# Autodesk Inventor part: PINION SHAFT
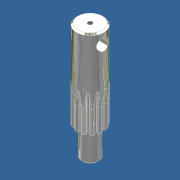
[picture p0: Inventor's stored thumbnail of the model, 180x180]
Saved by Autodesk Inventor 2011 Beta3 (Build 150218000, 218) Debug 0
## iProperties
Shininess: 64.0
Length Units: 11269
Angle Units: 11279
Time Units: 11290
Mass Units: 11283
Length Display Precision: 3
Angle Display Precision: 2
Compacted: True
Part Number: PINION SHAFT
Document SubType Name: Modeling
Created: 2003-10
Designer: Autodesk, Inc.
Manufacturer: Standard
Standards Organization: Custom
Mass: 506.446 g
Surface Area: 152.229 cm^2
Volume: 64.5977 cm^3
Density: 7.84 g/cm^3
Material: Steel, High Strength Low Alloy
Density: 0.0
Volumn: 0.0
Area: 0.0
PropertySet Name: Model Information
Control State: 0
Master: False
Checked Out: False
Author: Autodesk, Inc.
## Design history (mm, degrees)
sketch "Sketch1" dims "d4" = 6.7945 (= Big_R), "d5" = 5.54567 (= 2 x little_r)
  geometry: L1 (0, 12.7)-(5.815, 12.7); L2 (5.815, 12.7)-(5.815, 14.817); L3 (5.815, 14.817)-(0, 14.817); L4 (0, 14.817)-(0, 12.7); L5 (-8.163, 9.729)-(5.815, 14.817); L6 (0, 0)-(0, 10.251); L7 (0, 11.934)-(0, 12.7); L8 (0, 11.934)-(0, 10.251); L9 (-0.191, 11.933)-(-0.184, 10.731); L10 (0, 0)-(1.934, 14.69); L11 (0, 0)-(-1.338, 10.163); L12 (0, 0)-(3.923, 9.471); L13 (3.273, 11.477)-(2.955, 10.318); L14 (-0.181, 10.249)-(-0.184, 10.731); A1 r 12.7 centre (0, 0) between (0, 12.7) and (-8.163, 9.729); A2 r 14.817 centre (0, 0) between (0, 14.817) and (1.934, 14.69); A3 r 11.934 centre (0, 0) between (0, 11.934) and (6.294, 10.14); A4 r 10.251 centre (0, 0) between (0, 10.251) and (-0.181, 10.249); A5 r 6.795 centre (6.294, 10.14) between (1.365, 14.817) and (0, 12.7); A6 r 2.773 centre (2.568, 11.654) between (0, 12.7) and (-0.191, 11.933); A7 r 10.251 centre (0, 0) between (-0.651, 10.23) and (-1.338, 10.163); A8 r 0.498 centre (-0.682, 10.728) between (-0.651, 10.23) and (-0.184, 10.731); A9 r 10.251 centre (0, 0) between (3.923, 9.471) and (3.276, 9.713); A10 r 0.498 centre (3.435, 10.186) between (2.955, 10.318) and (3.276, 9.713); A11 r 2.773 centre (0.536, 11.922) between (3.273, 11.477) and (3.287, 12.267); A12 r 6.795 centre (-3.455, 11.423) between (3.287, 12.267) and (2.516, 14.665); A13 r 14.879 centre (0, 0) between (2.516, 14.665) and (1.365, 14.817); 2 further points; 1 other entity
  constraints: 30 point on circle, 28 end point, 13 centre point, 9 coincident, 9 symmetric about line, 4 tangent, 3 point on line, 2 parallel, 2 vertical, 1 collinear, 1 horizontal, 1 perpendicular, 16 other
  dimensions: "d0" = 25.4 diameter of A1 (= Pitch_Diameter); "d1" = 2.11667 distance of L1.end L2.end (= Addendum); "d2" = 20 deg angle of L1 L5 (= Tooth_Form); "d3" = 4.56565 distance of L6.end L3.end (= Whole_Depth); "d6" = 7.5 deg angle of L10 L6 (= mirror_angle); "d7" = 7.5 deg angle of L11 L6 (= mirror_angle); "d8" = 0.49848 radius of A8 (= Root_Fillet)
extrude "Extrusion1" new body sketch "Sketch1" distance "d9" = 25.4; taper "d10" = 0 deg
pattern_circular "Circular Pattern1" dims angle "d13" = 360 deg
sketch "Sketch2"
  geometry: C1 r 14.879 at (0, 0); 1 further point
  constraints: 1 centre point, 1 coincident
  dimensions: "d14" = 29.758 diameter of C1
extrude "Extrusion2" join sketch "Sketch2" distance "d15" = 71.4502; taper "d16" = 0 deg
sketch "Sketch3"
  geometry: C1 r 9.5 at (0, 0); 1 further point
  constraints: 1 centre point, 1 coincident
  dimensions: "d17" = 18.9992 diameter of C1
extrude "Extrusion3" join sketch "Sketch3" distance "d18" = 30.1498; taper "d19" = 0 deg
chamfer "Chamfer1" distance "d20" = 1.5875; stored, may be unused: second distance "d21" = 2, angle "d67" = 45 deg
chamfer "Chamfer2" distance "d22" = 1.5875; stored, may be unused: second distance "d23" = 2, angle "d68" = 45 deg
workplane "Work Plane2"
sketch "Sketch4"
  geometry: L1 (-13.292, 96.85)-(13.292, 96.85) reference; L2 (0, 96.85)-(0, 65.832); C1 r 6.54 at (0, 84.15)
  constraints: 2 end point, 1 centre point, 1 midpoint, 1 perpendicular, 1 point on line
  dimensions: "d26" = 13.081 diameter of C1; "d27" = 12.7 distance from line of L1 C1.centre
extrude "Extrusion4" cut sketch "Sketch4" distance "d28" = 50.8; taper "d29" = 0 deg
workplane "Work Plane3"
sketch "Sketch10"
  geometry: L1 (-5.206, 9.385)-(-5.801, 10.429) reference; L2 (-3.273, 11.477)-(-2.955, 10.318) reference; L3 (-5.801, 10.429)-(-5.206, 9.385); L4 (-2.955, 10.318)-(-3.273, 11.477); L5 (-30.301, 30.745)-(3.482, 44.738); L6 (-8.59, 12.149)-(-2.517, 14.665); L7 (0.184, 10.731)-(0.191, 11.933) reference; L8 (2.904, 11.575)-(2.6, 10.413) reference; L9 (0.191, 11.933)-(0.184, 10.731); L10 (2.904, 11.575)-(2.6, 10.413); L11 (5.524, 9.201)-(6.131, 10.239) reference; L12 (8.303, 8.572)-(7.458, 7.718) reference; L13 (5.524, 9.201)-(6.131, 10.239); L14 (7.458, 7.718)-(8.303, 8.572); L15 (9.385, 5.206)-(10.429, 5.801) reference; L16 (11.477, 3.273)-(10.318, 2.955) reference; L17 (9.385, 5.206)-(10.429, 5.801); L18 (11.477, 3.273)-(10.318, 2.955); A1 r 6.795 centre (3.455, 11.423) between (-2.517, 14.665) and (-3.287, 12.267) reference; A2 r 14.879 centre (0, 0) between (-2.517, 14.665) and (-8.59, 12.149) reference; A3 r 6.795 centre (-10.52, 5.634) between (-6.35, 10.999) and (-8.59, 12.149) reference; A4 r 2.773 centre (-8.051, 8.809) between (-5.801, 10.429) and (-6.35, 10.999) reference; A5 r 0.498 centre (-4.773, 9.632) between (-5.206, 9.385) and (-4.552, 9.185) reference; A6 r 10.251 centre (0, 0) between (-3.276, 9.713) and (-4.552, 9.185) reference; A7 r 0.498 centre (-3.435, 10.186) between (-3.276, 9.713) and (-2.955, 10.318) reference; A8 r 2.773 centre (-0.536, 11.922) between (-3.287, 12.267) and (-3.273, 11.477) reference; A9 r 14.879 centre (0, 0) between (-2.517, 14.665) and (-8.59, 12.149); A10 r 6.795 centre (-10.52, 5.634) between (-6.35, 10.999) and (-8.59, 12.149); A11 r 2.773 centre (-8.051, 8.809) between (-5.801, 10.429) and (-6.35, 10.999); A12 r 0.498 centre (-4.773, 9.632) between (-5.206, 9.385) and (-4.552, 9.185); A13 r 10.251 centre (0, 0) between (-3.276, 9.713) and (-4.552, 9.185); A14 r 6.795 centre (3.455, 11.423) between (-2.517, 14.665) and (-3.287, 12.267); A15 r 2.773 centre (-0.536, 11.922) between (-3.287, 12.267) and (-3.273, 11.477); A16 r 0.498 centre (-3.435, 10.186) between (-3.276, 9.713) and (-2.955, 10.318); A17 r 10.251 centre (0, 0) between (-3.276, 9.713) and (-4.552, 9.185) reference; A18 r 6.795 centre (8.704, 8.165) between (5.153, 13.958) and (3.287, 12.267) reference; A19 r 14.879 centre (0, 0) between (5.153, 13.958) and (-1.365, 14.816) reference; A20 r 6.795 centre (-6.294, 10.14) between (0, 12.7) and (-1.365, 14.816) reference; A21 r 2.773 centre (-2.568, 11.654) between (0.191, 11.933) and (0, 12.7) reference; A22 r 0.498 centre (0.682, 10.728) between (0.184, 10.731) and (0.651, 10.23) reference; A23 r 10.251 centre (0, 0) between (2.019, 10.05) and (0.651, 10.23) reference; A24 r 0.498 centre (2.118, 10.539) between (2.019, 10.05) and (2.6, 10.413) reference; A25 r 2.773 centre (5.497, 10.593) between (3.287, 12.267) and (2.904, 11.575) reference; A26 r 6.795 centre (-6.294, 10.14) between (0, 12.7) and (-1.365, 14.816); A27 r 2.773 centre (-2.568, 11.654) between (0.191, 11.933) and (0, 12.7); A28 r 0.498 centre (0.682, 10.728) between (0.184, 10.731) and (0.651, 10.23); A29 r 0.498 centre (2.118, 10.539) between (2.019, 10.05) and (2.6, 10.413); A30 r 2.773 centre (5.497, 10.593) between (3.287, 12.267) and (2.904, 11.575); A31 r 6.795 centre (8.704, 8.165) between (5.153, 13.958) and (3.287, 12.267); A32 r 14.879 centre (0, 0) between (5.153, 13.958) and (-1.365, 14.816); A33 r 10.251 centre (0, 0) between (2.019, 10.05) and (0.651, 10.23); A34 r 6.795 centre (11.62, 2.72) between (11.442, 9.512) and (8.98, 8.98) reference; A35 r 14.879 centre (0, 0) between (11.442, 9.512) and (6.226, 13.514) reference; A36 r 6.795 centre (-0.381, 11.928) between (6.35, 10.999) and (6.226, 13.514) reference; A37 r 2.773 centre (3.603, 11.377) between (6.131, 10.239) and (6.35, 10.999) reference; A38 r 0.498 centre (5.955, 8.949) between (5.524, 9.201) and (5.679, 8.534) reference; A39 r 10.251 centre (0, 0) between (6.774, 7.694) and (5.679, 8.534) reference; A40 r 0.498 centre (7.103, 8.068) between (6.774, 7.694) and (7.458, 7.718) reference; A41 r 2.773 centre (10.057, 6.425) between (8.98, 8.98) and (8.303, 8.572) reference; A42 r 14.879 centre (0, 0) between (11.442, 9.512) and (6.226, 13.514); A43 r 6.795 centre (-0.381, 11.928) between (6.35, 10.999) and (6.226, 13.514); A44 r 2.773 centre (3.603, 11.377) between (6.131, 10.239) and (6.35, 10.999); A45 r 0.498 centre (5.955, 8.949) between (5.524, 9.201) and (5.679, 8.534); A46 r 0.498 centre (7.103, 8.068) between (6.774, 7.694) and (7.458, 7.718); A47 r 2.773 centre (10.057, 6.425) between (8.98, 8.98) and (8.303, 8.572); A48 r 6.795 centre (11.62, 2.72) between (11.442, 9.512) and (8.98, 8.98); A49 r 10.251 centre (0, 0) between (6.774, 7.694) and (5.679, 8.534); A50 r 6.795 centre (11.423, -3.455) between (14.665, 2.517) and (12.267, 3.287) reference; A51 r 14.879 centre (0, 0) between (14.665, 2.517) and (12.149, 8.59) reference; A52 r 6.795 centre (5.634, 10.52) between (10.999, 6.35) and (12.149, 8.59) reference; A53 r 2.773 centre (8.809, 8.051) between (10.429, 5.801) and (10.999, 6.35) reference; A54 r 0.498 centre (9.632, 4.773) between (9.385, 5.206) and (9.185, 4.552) reference; A55 r 10.251 centre (0, 0) between (9.713, 3.276) and (9.185, 4.552) reference; A56 r 0.498 centre (10.186, 3.435) between (9.713, 3.276) and (10.318, 2.955) reference; A57 r 2.773 centre (11.922, 0.536) between (12.267, 3.287) and (11.477, 3.273) reference; A58 r 10.251 centre (0, 0) between (9.713, 3.276) and (9.185, 4.552); A59 r 0.498 centre (9.632, 4.773) between (9.385, 5.206) and (9.185, 4.552); A60 r 0.498 centre (10.186, 3.435) between (9.713, 3.276) and (10.318, 2.955); A61 r 2.773 centre (11.922, 0.536) between (12.267, 3.287) and (11.477, 3.273); A62 r 2.773 centre (8.809, 8.051) between (10.429, 5.801) and (10.999, 6.35); A63 r 6.795 centre (5.634, 10.52) between (10.999, 6.35) and (12.149, 8.59); A64 r 6.794 centre (11.423, -3.455) between (14.665, 2.517) and (12.267, 3.287)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
  constraints: 66 point on circle, 32 centre point, 30 concentric, 27 tangent, 20 end point, 8 collinear, 1 parallel
  dimensions: "d32" = 40 distance from line of L5 A17.centre
revolve "Revolution1" sketch "Sketch10" stored, may be unused: angle "d33" = 90 deg
sketch "Sketch11"
  geometry: L1 (0.184, 10.731)-(0.191, 11.933) reference; L2 (2.904, 11.575)-(2.6, 10.413) reference; L3 (0.184, 10.731)-(0.191, 11.933); L4 (2.6, 10.413)-(2.904, 11.575); L5 (-8.56, 41.472)-(25.088, 37.042); L6 (-1.365, 14.816)-(5.153, 13.958); C1 r 7.912 at (0, 0) reference; A1 r 6.795 centre (8.704, 8.165) between (5.153, 13.958) and (3.287, 12.267) reference; A2 r 14.879 centre (0, 0) between (5.153, 13.958) and (-1.365, 14.816) reference; A3 r 6.795 centre (-6.294, 10.14) between (0, 12.7) and (-1.365, 14.816) reference; A4 r 2.773 centre (-2.568, 11.654) between (0.191, 11.933) and (0, 12.7) reference; A5 r 0.498 centre (0.682, 10.728) between (0.184, 10.731) and (0.651, 10.23) reference; A6 r 10.251 centre (0, 0) between (2.019, 10.05) and (0.651, 10.23) reference; A7 r 0.498 centre (2.118, 10.539) between (2.019, 10.05) and (2.6, 10.413) reference; A8 r 2.773 centre (5.497, 10.593) between (3.287, 12.267) and (2.904, 11.575) reference; A9 r 14.879 centre (0, 0) between (5.153, 13.958) and (-1.365, 14.816); A10 r 6.795 centre (-6.294, 10.14) between (0, 12.7) and (-1.365, 14.816); A11 r 2.773 centre (-2.568, 11.654) between (0.191, 11.933) and (0, 12.7); A12 r 0.498 centre (0.682, 10.728) between (0.184, 10.731) and (0.651, 10.23); A13 r 10.251 centre (0, 0) between (2.019, 10.05) and (0.651, 10.23); A14 r 6.795 centre (8.704, 8.165) between (5.153, 13.958) and (3.287, 12.267); A15 r 2.773 centre (5.497, 10.593) between (3.287, 12.267) and (2.904, 11.575); A16 r 0.498 centre (2.118, 10.539) between (2.019, 10.05) and (2.6, 10.413)
  constraints: 16 point on circle, 8 centre point, 8 end point, 8 tangent, 6 concentric, 2 collinear, 1 parallel
  dimensions: "d35" = 40 distance from line of C1.centre L5
revolve "Revolution2" sketch "Sketch11" stored, may be unused: angle "d36" = 90 deg
sketch "Sketch12"
  geometry: L1 (5.524, 9.201)-(6.131, 10.239) reference; L2 (8.303, 8.572)-(7.458, 7.718) reference; L3 (8.303, 8.572)-(7.458, 7.718); L4 (5.524, 9.201)-(6.131, 10.239); L5 (37.465, 21.671)-(7.155, 44.928); L6 (11.442, 9.512)-(6.226, 13.514); C1 r 7.912 at (0, 0) reference; A1 r 6.795 centre (11.62, 2.72) between (11.442, 9.512) and (8.98, 8.98) reference; A2 r 14.879 centre (0, 0) between (11.442, 9.512) and (6.226, 13.514) reference; A3 r 6.795 centre (-0.381, 11.928) between (6.35, 10.999) and (6.226, 13.514) reference; A4 r 2.773 centre (3.603, 11.377) between (6.131, 10.239) and (6.35, 10.999) reference; A5 r 0.498 centre (5.955, 8.949) between (5.524, 9.201) and (5.679, 8.534) reference; A6 r 10.251 centre (0, 0) between (6.774, 7.694) and (5.679, 8.534) reference; A7 r 0.498 centre (7.103, 8.068) between (6.774, 7.694) and (7.458, 7.718) reference; A8 r 2.773 centre (10.057, 6.425) between (8.98, 8.98) and (8.303, 8.572) reference; A9 r 14.879 centre (0, 0) between (11.442, 9.512) and (6.226, 13.514); A10 r 0.498 centre (5.955, 8.949) between (5.524, 9.201) and (5.679, 8.534); A11 r 6.795 centre (-0.381, 11.928) between (6.35, 10.999) and (6.226, 13.514); A12 r 2.773 centre (3.603, 11.377) between (6.131, 10.239) and (6.35, 10.999); A13 r 0.498 centre (7.103, 8.068) between (6.774, 7.694) and (7.458, 7.718); A14 r 2.773 centre (10.057, 6.425) between (8.98, 8.98) and (8.303, 8.572); A15 r 6.795 centre (11.62, 2.72) between (11.442, 9.512) and (8.98, 8.98); A16 r 10.251 centre (0, 0) between (6.774, 7.694) and (5.679, 8.534)
  constraints: 16 point on circle, 8 centre point, 8 end point, 7 concentric, 7 tangent, 2 collinear, 1 parallel
  dimensions: "d37" = 40 distance from line of C1.centre L5
revolve "Revolution3" sketch "Sketch12" stored, may be unused: angle "d38" = 90 deg
sketch "Sketch13"
  geometry: L1 (9.385, 5.206)-(10.429, 5.801) reference; L2 (11.477, 3.273)-(10.318, 2.955) reference; L3 (9.385, 5.206)-(10.429, 5.801); L4 (10.318, 2.955)-(11.477, 3.273); L5 (14.665, 2.517)-(12.149, 8.59); L6 (43.302, -0.015)-(26.182, 41.316); C1 r 7.912 at (0, 0) reference; A1 r 6.795 centre (11.423, -3.455) between (14.665, 2.517) and (12.267, 3.287) reference; A2 r 14.879 centre (0, 0) between (14.665, 2.517) and (12.149, 8.59) reference; A3 r 6.795 centre (5.634, 10.52) between (10.999, 6.35) and (12.149, 8.59) reference; A4 r 2.773 centre (8.809, 8.051) between (10.429, 5.801) and (10.999, 6.35) reference; A5 r 0.498 centre (9.632, 4.773) between (9.385, 5.206) and (9.185, 4.552) reference; A6 r 10.251 centre (0, 0) between (9.713, 3.276) and (9.185, 4.552) reference; A7 r 0.498 centre (10.186, 3.435) between (9.713, 3.276) and (10.318, 2.955) reference; A8 r 2.773 centre (11.922, 0.536) between (12.267, 3.287) and (11.477, 3.273) reference; A9 r 6.795 centre (5.634, 10.52) between (10.999, 6.35) and (12.149, 8.59); A10 r 2.773 centre (8.809, 8.051) between (10.429, 5.801) and (10.999, 6.35); A11 r 0.498 centre (9.632, 4.773) between (9.385, 5.206) and (9.185, 4.552); A12 r 0.498 centre (10.186, 3.435) between (9.713, 3.276) and (10.318, 2.955); A13 r 2.773 centre (11.922, 0.536) between (12.267, 3.287) and (11.477, 3.273); A14 r 10.251 centre (0, 0) between (9.713, 3.276) and (9.185, 4.552); A15 r 6.795 centre (11.423, -3.455) between (14.665, 2.517) and (12.267, 3.287); A16 r 14.879 centre (0, 0) between (14.665, 2.517) and (12.149, 8.59)
  constraints: 16 point on circle, 8 centre point, 8 concentric, 8 end point, 2 collinear, 2 tangent, 1 parallel
  dimensions: "d39" = 40 distance from line of C1.centre L6
  node "Projected Loop8"
sketch "Sketch14"
  geometry: L1 (-9.201, 5.524)-(-10.239, 6.131) reference; L2 (-8.572, 8.303)-(-7.718, 7.458) reference; L3 (-9.201, 5.524)-(-10.239, 6.131); L4 (-7.718, 7.458)-(-8.572, 8.303); L5 (-13.514, 6.226)-(-9.512, 11.442); L6 (-43.85, 8.561)-(-20.3, 39.252); C1 r 7.912 at (0, 0) reference; A1 r 6.795 centre (-11.928, -0.381) between (-10.999, 6.35) and (-13.514, 6.226) reference; A2 r 2.773 centre (-11.377, 3.603) between (-10.239, 6.131) and (-10.999, 6.35) reference; A3 r 0.498 centre (-8.949, 5.955) between (-9.201, 5.524) and (-8.534, 5.679) reference; A4 r 10.251 centre (0, 0) between (-7.694, 6.774) and (-8.534, 5.679) reference; A5 r 0.498 centre (-8.068, 7.103) between (-7.694, 6.774) and (-7.718, 7.458) reference; A6 r 2.773 centre (-6.425, 10.057) between (-8.98, 8.98) and (-8.572, 8.303) reference; A7 r 6.795 centre (-2.72, 11.62) between (-9.512, 11.442) and (-8.98, 8.98) reference; A8 r 14.879 centre (0, 0) between (-9.512, 11.442) and (-13.514, 6.226) reference; A9 r 14.879 centre (0, 0) between (-9.512, 11.442) and (-13.514, 6.226); A10 r 0.498 centre (-8.949, 5.955) between (-9.201, 5.524) and (-8.534, 5.679); A11 r 2.773 centre (-11.377, 3.603) between (-10.239, 6.131) and (-10.999, 6.35); A12 r 6.795 centre (-11.928, -0.381) between (-10.999, 6.35) and (-13.514, 6.226); A13 r 6.795 centre (-2.72, 11.62) between (-9.512, 11.442) and (-8.98, 8.98); A14 r 2.773 centre (-6.425, 10.057) between (-8.98, 8.98) and (-8.572, 8.303); A15 r 10.251 centre (0, 0) between (-7.694, 6.774) and (-8.534, 5.679); A16 r 0.498 centre (-8.068, 7.103) between (-7.694, 6.774) and (-7.718, 7.458)
  constraints: 17 point on circle, 8 centre point, 8 end point, 8 tangent, 6 concentric, 2 collinear, 1 parallel
  dimensions: "d40" = 40 distance from line of C1.centre L6
revolve "Revolution5" sketch "Sketch14" stored, may be unused: angle "d42" = 90 deg
revolve "Revolution6" stored, may be unused: angle "d43" = 90 deg
sketch "Sketch15"
  geometry: L1 (10.731, -0.184)-(11.933, -0.191) reference; L2 (11.575, -2.904)-(10.413, -2.6) reference; L3 (10.731, -0.184)-(11.933, -0.191); L4 (10.413, -2.6)-(11.575, -2.904); L5 (13.958, -5.153)-(14.816, 1.365); L6 (42.416, 15.732)-(37.273, -23.332); C1 r 7.912 at (0, 0) reference; A1 r 6.795 centre (8.165, -8.704) between (13.958, -5.153) and (12.267, -3.287) reference; A2 r 14.879 centre (0, 0) between (13.958, -5.153) and (14.816, 1.365) reference; A3 r 6.795 centre (10.14, 6.294) between (12.7, 0) and (14.816, 1.365) reference; A4 r 2.773 centre (11.654, 2.568) between (11.933, -0.191) and (12.7, 0) reference; A5 r 0.498 centre (10.728, -0.682) between (10.731, -0.184) and (10.23, -0.651) reference; A6 r 10.251 centre (0, 0) between (10.05, -2.019) and (10.23, -0.651) reference; A7 r 0.498 centre (10.539, -2.118) between (10.05, -2.019) and (10.413, -2.6) reference; A8 r 2.773 centre (10.593, -5.497) between (12.267, -3.287) and (11.575, -2.904) reference; A9 r 14.879 centre (0, 0) between (13.958, -5.153) and (14.816, 1.365); A10 r 6.795 centre (10.14, 6.294) between (12.7, 0) and (14.816, 1.365); A11 r 2.773 centre (11.654, 2.568) between (11.933, -0.191) and (12.7, 0); A12 r 0.498 centre (10.728, -0.682) between (10.731, -0.184) and (10.23, -0.651); A13 r 10.251 centre (0, 0) between (10.05, -2.019) and (10.23, -0.651); A14 r 0.498 centre (10.539, -2.118) between (10.05, -2.019) and (10.413, -2.6); A15 r 2.773 centre (10.593, -5.497) between (12.267, -3.287) and (11.575, -2.904); A16 r 6.795 centre (8.165, -8.704) between (13.958, -5.153) and (12.267, -3.287)
  constraints: 16 point on circle, 8 centre point, 8 concentric, 8 end point, 5 tangent, 2 collinear, 1 parallel
  dimensions: "d44" = 40 distance from line of C1.centre L6
revolve "Revolution7" sketch "Sketch15" stored, may be unused: angle "d45" = 90 deg
sketch "Sketch16"
  geometry: L1 (9.201, -5.524)-(10.239, -6.131) reference; L2 (8.572, -8.303)-(7.718, -7.458) reference; L3 (9.201, -5.524)-(10.239, -6.131); L4 (7.718, -7.458)-(8.572, -8.303); L5 (9.512, -11.442)-(13.514, -6.226); L6 (22.205, -36.769)-(41.695, -11.369); C1 r 7.912 at (0, 0) reference; A1 r 6.795 centre (2.72, -11.62) between (9.512, -11.442) and (8.98, -8.98) reference; A2 r 14.879 centre (0, 0) between (9.512, -11.442) and (13.514, -6.226) reference; A3 r 6.795 centre (11.928, 0.381) between (10.999, -6.35) and (13.514, -6.226) reference; A4 r 2.773 centre (11.377, -3.603) between (10.239, -6.131) and (10.999, -6.35) reference; A5 r 0.498 centre (8.949, -5.955) between (9.201, -5.524) and (8.534, -5.679) reference; A6 r 10.251 centre (0, 0) between (7.694, -6.774) and (8.534, -5.679) reference; A7 r 0.498 centre (8.068, -7.103) between (7.694, -6.774) and (7.718, -7.458) reference; A8 r 2.773 centre (6.425, -10.057) between (8.98, -8.98) and (8.572, -8.303) reference; A9 r 14.879 centre (0, 0) between (9.512, -11.442) and (13.514, -6.226); A10 r 6.795 centre (11.928, 0.381) between (10.999, -6.35) and (13.514, -6.226); A11 r 2.773 centre (11.377, -3.603) between (10.239, -6.131) and (10.999, -6.35); A12 r 0.498 centre (8.949, -5.955) between (9.201, -5.524) and (8.534, -5.679); A13 r 0.498 centre (8.068, -7.103) between (7.694, -6.774) and (7.718, -7.458); A14 r 2.773 centre (6.425, -10.057) between (8.98, -8.98) and (8.572, -8.303); A15 r 6.795 centre (2.72, -11.62) between (9.512, -11.442) and (8.98, -8.98); A16 r 10.251 centre (0, 0) between (7.694, -6.774) and (8.534, -5.679)
  constraints: 18 point on circle, 9 tangent, 8 centre point, 8 end point, 6 concentric, 2 collinear, 1 parallel
  dimensions: "d51" = 40 distance from line of C1.centre L6
revolve "Revolution8" sketch "Sketch16" stored, may be unused: angle "d48" = 90 deg
sketch "Sketch17"
  geometry: L1 (5.206, -9.385)-(5.801, -10.429) reference; L2 (3.273, -11.477)-(2.955, -10.318) reference; L3 (5.206, -9.385)-(5.801, -10.429); L4 (2.955, -10.318)-(3.273, -11.477); L5 (8.59, -12.149)-(2.517, -14.665); L6 (-1.988, -44.119)-(32.429, -29.863); C1 r 7.912 at (0, 0) reference; A1 r 6.795 centre (10.52, -5.634) between (6.35, -10.999) and (8.59, -12.149) reference; A2 r 2.773 centre (8.051, -8.809) between (5.801, -10.429) and (6.35, -10.999) reference; A3 r 0.498 centre (4.773, -9.632) between (5.206, -9.385) and (4.552, -9.185) reference; A4 r 10.251 centre (0, 0) between (3.276, -9.713) and (4.552, -9.185) reference; A5 r 0.498 centre (3.435, -10.186) between (3.276, -9.713) and (2.955, -10.318) reference; A6 r 2.773 centre (0.536, -11.922) between (3.287, -12.267) and (3.273, -11.477) reference; A7 r 6.795 centre (-3.455, -11.423) between (2.517, -14.665) and (3.287, -12.267) reference; A8 r 14.879 centre (0, 0) between (2.517, -14.665) and (8.59, -12.149) reference; A9 r 14.879 centre (0, 0) between (2.517, -14.665) and (8.59, -12.149); A10 r 6.795 centre (-3.455, -11.423) between (2.517, -14.665) and (3.287, -12.267); A11 r 2.773 centre (0.536, -11.922) between (3.287, -12.267) and (3.273, -11.477); A12 r 0.498 centre (3.435, -10.186) between (3.276, -9.713) and (2.955, -10.318); A13 r 0.498 centre (4.773, -9.632) between (5.206, -9.385) and (4.552, -9.185); A14 r 6.795 centre (10.52, -5.634) between (6.35, -10.999) and (8.59, -12.149); A15 r 2.773 centre (8.051, -8.809) between (5.801, -10.429) and (6.35, -10.999); A16 r 10.251 centre (0, 0) between (3.276, -9.713) and (4.552, -9.185)
  constraints: 17 point on circle, 8 centre point, 8 end point, 7 concentric, 5 tangent, 2 collinear, 1 parallel
  dimensions: "d49" = 40 distance from line of C1.centre L6
revolve "Revolution9" sketch "Sketch17" stored, may be unused: angle "d50" = 90 deg
sketch "Sketch18"
  geometry: L1 (-0.184, -10.731)-(-0.191, -11.933) reference; L2 (-2.904, -11.575)-(-2.6, -10.413) reference; L3 (-0.184, -10.731)-(-0.191, -11.933); L4 (-2.6, -10.413)-(-2.904, -11.575); L5 (-5.153, -13.958)-(1.365, -14.816); L6 (18.309, -42.756)-(-25.099, -37.041); C1 r 7.912 at (0, 0) reference; A1 r 6.795 centre (6.294, -10.14) between (0, -12.7) and (1.365, -14.816) reference; A2 r 2.773 centre (2.568, -11.654) between (-0.191, -11.933) and (0, -12.7) reference; A3 r 0.498 centre (-0.682, -10.728) between (-0.184, -10.731) and (-0.651, -10.23) reference; A4 r 10.251 centre (0, 0) between (-2.019, -10.05) and (-0.651, -10.23) reference; A5 r 0.498 centre (-2.118, -10.539) between (-2.019, -10.05) and (-2.6, -10.413) reference; A6 r 2.773 centre (-5.497, -10.593) between (-3.287, -12.267) and (-2.904, -11.575) reference; A7 r 6.795 centre (-8.704, -8.165) between (-5.153, -13.958) and (-3.287, -12.267) reference; A8 r 14.879 centre (0, 0) between (-5.153, -13.958) and (1.365, -14.816) reference; A9 r 14.879 centre (0, 0) between (-5.153, -13.958) and (1.365, -14.816); A10 r 6.795 centre (6.294, -10.14) between (0, -12.7) and (1.365, -14.816); A11 r 0.498 centre (-0.682, -10.728) between (-0.184, -10.731) and (-0.651, -10.23); A12 r 2.773 centre (2.568, -11.654) between (-0.191, -11.933) and (0, -12.7); A13 r 6.795 centre (-8.704, -8.165) between (-5.153, -13.958) and (-3.287, -12.267); A14 r 2.773 centre (-5.497, -10.593) between (-3.287, -12.267) and (-2.904, -11.575); A15 r 0.498 centre (-2.118, -10.539) between (-2.019, -10.05) and (-2.6, -10.413); A16 r 10.251 centre (0, 0) between (-2.019, -10.05) and (-0.651, -10.23)
  constraints: 16 point on circle, 9 tangent, 8 centre point, 8 end point, 6 concentric, 2 collinear, 1 parallel
  dimensions: "d52" = 40 distance from line of L6 C1.centre
revolve "Revolution10" sketch "Sketch18" stored, may be unused: angle "d53" = 90 deg
sketch "Sketch19"
  geometry: L1 (-5.524, -9.201)-(-6.131, -10.239) reference; L2 (-8.303, -8.572)-(-7.458, -7.718) reference; L3 (-5.524, -9.201)-(-6.131, -10.239); L4 (-7.458, -7.718)-(-8.303, -8.572); L5 (-11.442, -9.512)-(-6.226, -13.514); L6 (-14.257, -39.479)-(-36.918, -22.091); C1 r 7.912 at (0, 0) reference; A1 r 6.795 centre (0.381, -11.928) between (-6.35, -10.999) and (-6.226, -13.514) reference; A2 r 2.773 centre (-3.603, -11.377) between (-6.131, -10.239) and (-6.35, -10.999) reference; A3 r 0.498 centre (-5.955, -8.949) between (-5.524, -9.201) and (-5.679, -8.534) reference; A4 r 10.251 centre (0, 0) between (-6.774, -7.694) and (-5.679, -8.534) reference; A5 r 0.498 centre (-7.103, -8.068) between (-6.774, -7.694) and (-7.458, -7.718) reference; A6 r 2.773 centre (-10.057, -6.425) between (-8.98, -8.98) and (-8.303, -8.572) reference; A7 r 6.795 centre (-11.62, -2.72) between (-11.442, -9.512) and (-8.98, -8.98) reference; A8 r 14.879 centre (0, 0) between (-11.442, -9.512) and (-6.226, -13.514) reference; A9 r 14.879 centre (0, 0) between (-11.442, -9.512) and (-6.226, -13.514); A10 r 6.795 centre (0.381, -11.928) between (-6.35, -10.999) and (-6.226, -13.514); A11 r 0.498 centre (-5.955, -8.949) between (-5.524, -9.201) and (-5.679, -8.534); A12 r 0.498 centre (-7.103, -8.068) between (-6.774, -7.694) and (-7.458, -7.718); A13 r 6.795 centre (-11.62, -2.72) between (-11.442, -9.512) and (-8.98, -8.98); A14 r 10.251 centre (0, 0) between (-6.774, -7.694) and (-5.679, -8.534); A15 r 2.773 centre (-10.057, -6.425) between (-8.98, -8.98) and (-8.303, -8.572); A16 r 2.773 centre (-3.603, -11.377) between (-6.131, -10.239) and (-6.35, -10.999)
  constraints: 16 point on circle, 11 tangent, 8 centre point, 8 end point, 5 concentric, 2 collinear, 1 parallel
  dimensions: "d54" = 40 distance from line of C1.centre L6
revolve "Revolution11" sketch "Sketch19" stored, may be unused: angle "d55" = 90 deg
sketch "Sketch20"
  geometry: L1 (-9.385, -5.206)-(-10.429, -5.801) reference; L2 (-11.477, -3.273)-(-10.318, -2.955) reference; L3 (-9.385, -5.206)-(-10.429, -5.801); L4 (-10.318, -2.955)-(-11.477, -3.273); L5 (-14.665, -2.517)-(-12.149, -8.59); L6 (-31.542, -28.377)-(-43.268, -0.067); C1 r 7.912 at (0, 0) reference; A1 r 6.795 centre (-5.634, -10.52) between (-10.999, -6.35) and (-12.149, -8.59) reference; A2 r 2.773 centre (-8.809, -8.051) between (-10.429, -5.801) and (-10.999, -6.35) reference; A3 r 0.498 centre (-9.632, -4.773) between (-9.385, -5.206) and (-9.185, -4.552) reference; A4 r 10.251 centre (0, 0) between (-9.713, -3.276) and (-9.185, -4.552) reference; A5 r 0.498 centre (-10.186, -3.435) between (-9.713, -3.276) and (-10.318, -2.955) reference; A6 r 2.773 centre (-11.922, -0.536) between (-12.267, -3.287) and (-11.477, -3.273) reference; A7 r 6.795 centre (-11.423, 3.455) between (-14.665, -2.517) and (-12.267, -3.287) reference; A8 r 14.879 centre (0, 0) between (-14.665, -2.517) and (-12.149, -8.59) reference; A9 r 14.879 centre (0, 0) between (-14.665, -2.517) and (-12.149, -8.59); A10 r 6.795 centre (-11.423, 3.455) between (-14.665, -2.517) and (-12.267, -3.287); A11 r 6.795 centre (-5.634, -10.52) between (-10.999, -6.35) and (-12.149, -8.59); A12 r 0.498 centre (-9.632, -4.773) between (-9.385, -5.206) and (-9.185, -4.552); A13 r 0.498 centre (-10.186, -3.435) between (-9.713, -3.276) and (-10.318, -2.955); A14 r 2.773 centre (-11.922, -0.536) between (-12.267, -3.287) and (-11.477, -3.273); A15 r 2.773 centre (-8.809, -8.051) between (-10.429, -5.801) and (-10.999, -6.35); A16 r 10.251 centre (0, 0) between (-9.713, -3.276) and (-9.185, -4.552)
  constraints: 16 point on circle, 8 centre point, 8 end point, 7 concentric, 7 tangent, 2 collinear, 1 parallel
  dimensions: "d56" = 40 distance from line of C1.centre L6
revolve "Revolution12" sketch "Sketch20" stored, may be unused: angle "d57" = 90 deg
sketch "Sketch21"
  geometry: L1 (-10.731, 0.184)-(-11.933, 0.191) reference; L2 (-11.575, 2.904)-(-10.413, 2.6) reference; L3 (-10.731, 0.184)-(-11.933, 0.191); L4 (-10.413, 2.6)-(-11.575, 2.904); L5 (-13.958, 5.153)-(-14.816, -1.365); L6 (-37.606, 20.805)-(-41.538, -9.057); C1 r 7.912 at (0, 0) reference; A1 r 6.795 centre (-10.14, -6.294) between (-12.7, 0) and (-14.816, -1.365) reference; A2 r 2.773 centre (-11.654, -2.568) between (-11.933, 0.191) and (-12.7, 0) reference; A3 r 0.498 centre (-10.728, 0.682) between (-10.731, 0.184) and (-10.23, 0.651) reference; A4 r 10.251 centre (0, 0) between (-10.05, 2.019) and (-10.23, 0.651) reference; A5 r 0.498 centre (-10.539, 2.118) between (-10.05, 2.019) and (-10.413, 2.6) reference; A6 r 2.773 centre (-10.593, 5.497) between (-12.267, 3.287) and (-11.575, 2.904) reference; A7 r 6.795 centre (-8.165, 8.704) between (-13.958, 5.153) and (-12.267, 3.287) reference; A8 r 14.879 centre (0, 0) between (-13.958, 5.153) and (-14.816, -1.365) reference; A9 r 14.879 centre (0, 0) between (-13.958, 5.153) and (-14.816, -1.365); A10 r 6.795 centre (-10.14, -6.294) between (-12.7, 0) and (-14.816, -1.365); A11 r 0.498 centre (-10.728, 0.682) between (-10.731, 0.184) and (-10.23, 0.651); A12 r 0.498 centre (-10.539, 2.118) between (-10.05, 2.019) and (-10.413, 2.6); A13 r 2.773 centre (-10.593, 5.497) between (-12.267, 3.287) and (-11.575, 2.904); A14 r 2.773 centre (-11.654, -2.568) between (-11.933, 0.191) and (-12.7, 0); A15 r 6.795 centre (-8.165, 8.704) between (-13.958, 5.153) and (-12.267, 3.287); A16 r 10.251 centre (0, 0) between (-10.05, 2.019) and (-10.23, 0.651)
  constraints: 16 point on circle, 8 centre point, 8 end point, 6 concentric, 6 tangent, 2 collinear, 1 parallel
  dimensions: "d58" = 40 distance from line of C1.centre L6
revolve "Revolution13" sketch "Sketch21" stored, may be unused: angle "d59" = 90 deg
sketch "Sketch22"
  geometry: C1 r 13.292 at (0, 0) reference; 1 further point
  constraints: 1 coincident
hole "Hole1" sketch "Sketch22" at (0, 0) diameter "d60" = 4.978; stored, may be unused: countersink angle "d64" = 82 deg, drill point angle "d66" = 118 deg; dims "d61" = 6, "d62" = 4, "d63" = 2, "d65" = 8
body "Solid1"
node "Projected Loop2"
node "Projected Loop3"
node "Projected Loop4"
node "Projected Loop5"
node "Projected Loop6"
node "Projected Loop7"
node "Projected Loop9"
node "Projected Loop10"
node "Projected Loop11"
node "Projected Loop12"
node "Projected Loop13"
node "Projected Loop14"
node "Projected Loop15"
node "Projected Loop16"
node "Projected Loop17"
other parameters: "Tooth_Form" = 20 deg [user parameter; used in 1 equation term], "Pitch_Diameter" = 25.4 [user parameter; used in 1 equation term], "Addendum" = 2.11667 [user parameter; used in 1 equation term], "Whole_Depth" = 4.56565 [user parameter; used in 1 equation term], "Big_R" = 6.7945 [user parameter; used in 1 equation term], "little_r" = 2.77283 [user parameter; used in 1 equation term], "Root_Fillet" = 0.49848 [user parameter; used in 1 equation term], "mirror_angle" = 7.5 deg [user parameter; used in 2 equation terms], "d25" = 16.75
